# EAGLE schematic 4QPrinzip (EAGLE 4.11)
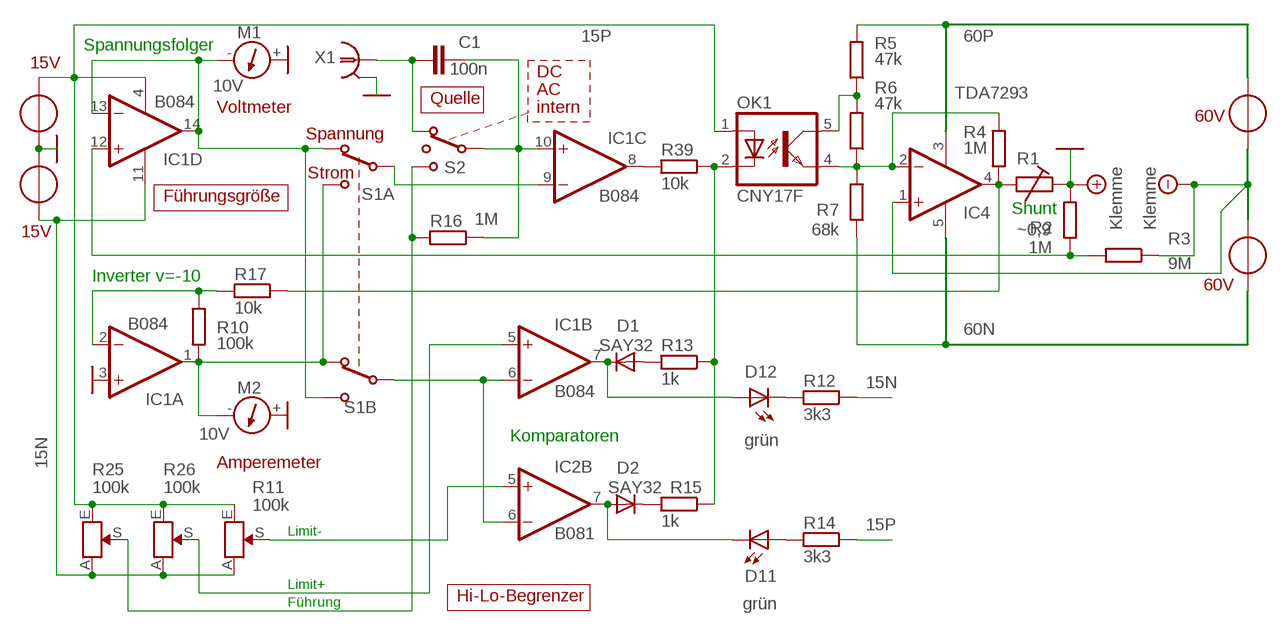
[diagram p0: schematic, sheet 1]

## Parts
C1  100n  C0805  [0805]
D1  SAY32  DIODE-D-10  [D-10]
D2  SAY32  DIODE-D-10  [D-10]
D11  grün  LED5MM  [LED5MM]
D12  grün  LED5MM  [LED5MM]
IC1  B084  TL084P  [DIL14]
IC2  B081  TL084P  [DIL14]
IC4  TDA7293  L165ST  [CB360]
M1  10V  MESSWERK  [MESSWERK]
M2  10V  MESSWERK  [MESSWERK]
OK1  CNY17F  [DIL06]
R1  ~0,9  RTRIM  [RTRIM]
R2  1M  R-EU_0207/10  [0207/10]
R3  9M  R-EU_0207/10  [0207/10]
R4  1M  R-EU_0207/10  [0207/10]
R5  47k  R-EU_0207/10  [0207/10]
R6  47k  R-EU_0207/10  [0207/10]
R7  68k  R-EU_0207/10  [0207/10]
R10  100k  R-EU_0207/10  [0207/10]
R11  100k  RPOT  [RPOT]
R12  3k3  R-EU_0207/10  [0207/10]
R13  1k  R-EU_0207/10  [0207/10]
R14  3k3  R-EU_0207/10  [0207/10]
R15  1k  R-EU_0207/10  [0207/10]
R16  1M  R-EU_0207/10  [0207/10]
R17  10k  R-EU_0207/10  [0207/10]
R25  100k  RPOT  [RPOT]
R26  100k  RPOT  [RPOT]
R39  10k  R-EU_0207/10  [0207/10]
S1A  U2  [U2]
S1B  U2  [U2]
S2  U3  [U2]
X1  A1944-50  [A1944]

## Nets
15N: IC1.11(P:V-) R11.A R12.1 R25.A R26.A
15P: IC1.4(P:V+) OK1.1(A) R11.E R14.1 R25.E R26.E
60N: IC4.5(V+) R7.1
60P: IC4.3(GND) R5.2
-UB: IC4.1(+IN) R3.1 ; supply symbol labelled Klemme
GND: IC1.3(A:+IN) M1.+ M2.+ R1.2 R2.1 X1.2(GND) ; supply symbol labelled Klemme
N$1: IC1.12(D:+IN) R2.2 R3.2
N$2: C1.2 IC1.10(C:+IN) R16.1 S2.S
N$3: IC4.2(-IN) OK1.4(EMIT) R4.2 R6.1 R7.2
N$4: IC1.13(D:-IN) IC1.14(D:OUT) M1.- S1A.S1 S1B.S2
N$5: IC1.8(C:OUT) R39.2
N$7: R16.2 R25.S S2.S2
N$9: OK1.2(C) R13.1 R15.1 R39.1
N$10: D1.C D12.A IC1.7(B:OUT)
N$11: D1.A R13.2
N$12: D2.A D11.K(C) IC2.7(B:OUT)
N$13: IC1.2(A:-IN) R10.1 R17.2
N$14: IC1.9(C:-IN) S1A.S
N$15: OK1.5(COL) R5.1 R6.2
N$18: IC1.1(A:OUT) M2.- R10.2 S1A.S2 S1B.S1
N$19: D2.C R15.2
N$21: D12.K(C) R12.2
N$22: D11.A R14.2
N$23: C1.1 S2.S1 X1.1
N$24: IC1.5(B:+IN) R26.S
N$25: IC2.5(B:+IN) R11.S
N$26: IC1.6(B:-IN) IC2.6(B:-IN) S1B.S
UO: IC4.4(OUT) R1.1 R4.1 R17.1
Unconnected: IC2.1(A:OUT) IC2.2(A:-IN) IC2.3(A:+IN) IC2.8(C:OUT) IC2.9(C:-IN) IC2.10(C:+IN) IC2.12(D:+IN) IC2.13(D:-IN) IC2.14(D:OUT)

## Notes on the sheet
- Spannungsfolger
- 15V
- DC
- AC
- Quelle
- Voltmeter | intern
- 60V
- Spannung
- Strom
- Führungsgröße
- Shunt
- 15V
- Inverter v=-10
- 60V
- Komparatoren
- Amperemeter
- Limit-
- Limit+
- Hi-Lo-Begrenzer
- Führung

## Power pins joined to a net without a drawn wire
GND: X1.3(GND) X1.4(GND) X1.5(GND)
V+: IC2.4(P:V+)
V-: IC2.11(P:V-)

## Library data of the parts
C1 = mv:C: Kondensator
D1 D2 = diode:DIODE-: DIODE
D11 D12 = led:LED: LED
IC1 IC2 = linear:TL084: OP AMP
IC4 = linear:L165ST: OP AMP
M1 M2 = statron:MESSWERK
OK1 = optocoupler:CNY17F: SIEMENS OPTO COUPLER
R1 = statron:RTRIM
R2-R7 R10 R12-R17 R39 = rcl:R-EU_: RESISTOR, European symbol
R11 R25 R26 = statron:RPOT
S1A S1B = statron:U2: Umschalter, 1-polig
S2 = statron:U3: Umschalter, 1-polig, mit kontaktloser Mittelstellung
X1 = con-coax:A1944-50: BNC CONNECTOR 50 Ohm distributor Buerklin 78F2475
